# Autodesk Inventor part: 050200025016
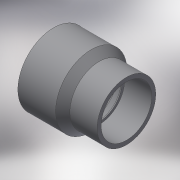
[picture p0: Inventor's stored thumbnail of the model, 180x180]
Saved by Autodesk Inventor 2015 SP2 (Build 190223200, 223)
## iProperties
Created: 2017-10
Part Number: 050200025016
Material: Generic
Description: PLASSON REDUCING SOCKET M.F.25(20)16 CEMENTED
Document SubType Name: Modeling
Designer: KIM
Density: 1 g/cm^3
Appearance: Default
Author: KIM
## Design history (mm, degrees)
derived "050200.ipt"
feature "Solid1::050200.ipt"
tag "TaggingFeature1"
body "Solid1"
other parameters: "d0" = 39, "d1" = 19, "d2" = 14, "d3" = 16, "d4" = 16, "d5" = 22, "d7" = 25, "d8" = 14.4, "d9" = 45 deg, "d12" = 0.2, "d_1" = 16, "L_" = 19, "l_" = 16, "l_1" = 14, "E_" = 22, "H_" = 39, "D_" = 25, "d11" = 2.44979
